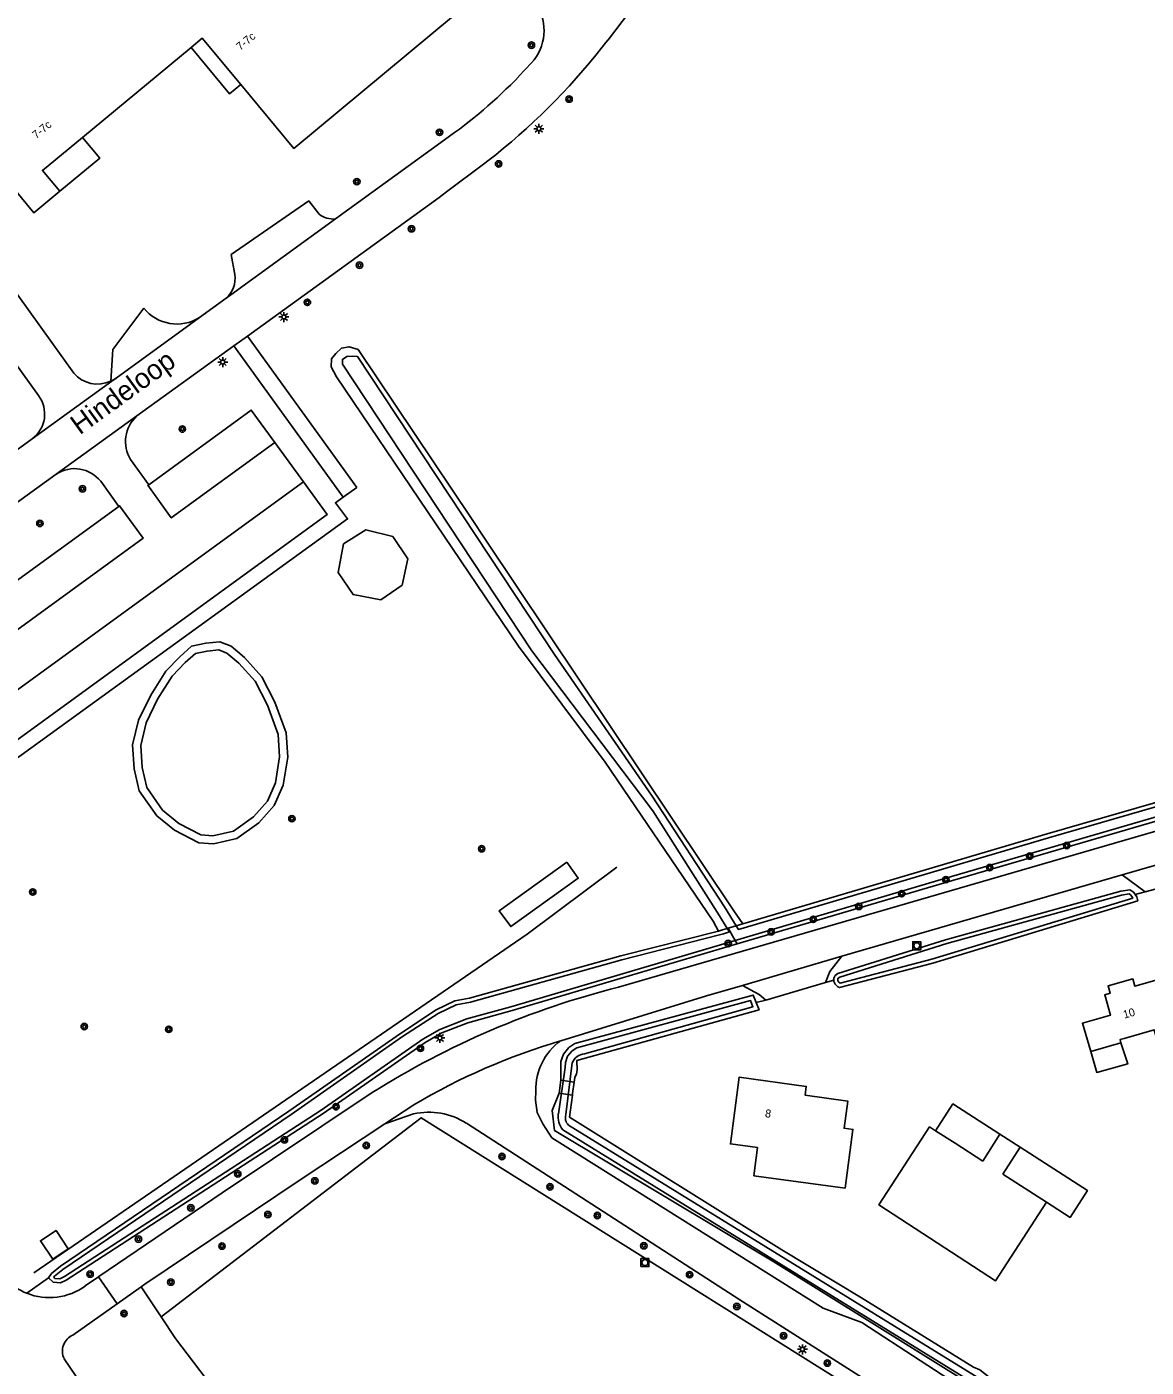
# Model space of a CAD drawing. Extents: x 141000 to 143000, y 400580 to 403500.
# Drawn here: x 141206 to 141345.9, y 402645.4 to 402812.9 of the extents above; entities that cross this region are included whole.
import ezdxf

# ---------------------------------------------------------------- set-up
doc = ezdxf.new("R2010")
doc.units = 0
for name, color, linetype in [('gg-afsc-erfafscheiding', 7, 'Continuous'), ('gg-afsc-hekwerk', 7, 'Continuous'), ('gg-anno-huisnummerreeks BGT', 7, 'Continuous'), ('gg-anno-openbare ruimte label', 7, 'Continuous'), ('gg-bbg-bijgebouw', 7, 'Continuous'), ('gg-bbg-gedigitaliseerde bijgebouw', 7, 'Continuous'), ('gg-bbg-hoofdgebouw', 7, 'Continuous'), ('gg-bbg-lage trafo', 7, 'Continuous'), ('gg-bbg-luifel en loopbrug', 7, 'Continuous'), ('gg-bbg-overig bouwwerk', 7, 'Continuous'), ('gg-knt-bronhoudergrens', 7, 'Continuous'), ('gg-knt-verharding', 7, 'Continuous'), ('gg-knt-verharding nz', 7, 'Continuous'), ('gg-kntw-bovenkant insteek waterloop', 7, 'Continuous'), ('gg-kntw-waterlijn', 7, 'Continuous'), ('gg-kwrk-kunstwerk niveau 01', 7, 'Continuous'), ('gt-grn-groengrens', 7, 'Continuous'), ('gt-grn-vlakafsluiter', 7, 'Continuous'), ('gt-grn-weggrens', 7, 'Continuous'), ('gt-symb-boom', 7, 'Continuous'), ('gt-symb-lichtmast', 7, 'Continuous'), ('gt-symb-rioolschacht', 7, 'Continuous')]:
    doc.layers.add(name, color=color, linetype=linetype)

# ---------------------------------------------------------------- blocks, each defined once
blk = doc.blocks.new('gt0-BOOM')
at = {"layer": 'gt-symb-boom'}
for radius in [0.4, 0.2]:
    blk.add_circle((0, 0), radius, dxfattribs=at)
blk = doc.blocks.new('gt0-LMAST')
at = {"layer": 'gt-symb-lichtmast'}
for p, q in [((-0.18, 0.17), (-0.45, 0.44)), ((-0.01, 0.25), (-0.01, 0.62)), ((0.17, 0.17), (0.44, 0.44)), ((-0.26, 0), (-0.63, 0)), ((-0.18, -0.18), (-0.45, -0.45)), ((-0.01, -0.25), (-0.01, -0.63)), ((0.44, -0.45), (0.17, -0.18)), ((0.24, 0), (0.62, 0))]:
    blk.add_line(p, q, dxfattribs=at)
blk.add_circle((-0.01, 0), 0.25, dxfattribs=at)
blk = doc.blocks.new('gt0-RS')
at = {"layer": 'gt-symb-rioolschacht'}
blk.add_lwpolyline([(-0.5, -0.5), (0.5, -0.5), (0.5, 0.5), (-0.5, 0.5)], close=True, dxfattribs=at)
blk.add_circle((0, 0), 0.375, dxfattribs=at)

msp = doc.modelspace()

# ---------------------------------------------------------------- linework, layer by layer
at = {"layer": 'gg-afsc-erfafscheiding'}
for p, q in [((141269.11, 402808.42), (141267.52, 402806.74)), ((141344.56, 402704.49), (141345.78, 402704.79)), ((141305.83, 402693.49), (141306.89, 402693.77)), ((141297.18, 402690.98), (141298.4, 402691.29))]:
    msp.add_line(p, q, dxfattribs=at)
at = {"layer": 'gg-afsc-hekwerk'}
msp.add_line((141245.56, 402754.13), (141247.27, 402755.33), dxfattribs=at)
for points in [[(141178.21, 402702.31), (141246.1, 402751.42), (141244.58, 402753.43), (141245.56, 402754.13)], [(141279.74, 402707.9), (141268.55, 402699.51), (141206.88, 402657.21)]]:
    msp.add_lwpolyline(points, dxfattribs=at)
at = {"layer": 'gg-bbg-bijgebouw'}
msp.add_line((141333.47, 402666.01), (141328.01, 402669.53), dxfattribs=at)
for points in [[(141319.61, 402674.95), (141318.86, 402675.43), (141312.52, 402665.67), (141327.1, 402656.2), (141333.47, 402666.01)], [(141325.49, 402671.16), (141322.04, 402673.38), (141319.61, 402674.95)]]:
    msp.add_lwpolyline(points, dxfattribs=at)
at = {"layer": 'gg-bbg-gedigitaliseerde bijgebouw'}
for p, q in [((141325.49, 402671.16), (141327.65, 402674.51)), ((141330.17, 402672.88), (141327.65, 402674.51)), ((141328.01, 402669.53), (141330.17, 402672.88))]:
    msp.add_line(p, q, dxfattribs=at)
at = {"layer": 'gg-bbg-hoofdgebouw'}
for p, q in [((141212.97, 402799.11), (141226.55, 402810.34)), ((141342.77, 402685.95), (141339, 402684.85))]:
    msp.add_line(p, q, dxfattribs=at)
for points in [[(141232.74, 402805.73), (141239.4, 402797.73), (141265, 402819.06), (141262.19, 402822.41), (141263.36, 402823.38)], [(141226.55, 402810.34), (141227.94, 402811.49), (141232.74, 402805.73)], [(141196.66, 402802.03), (141206.9, 402789.67), (141210.15, 402792.38)], [(141210.15, 402792.38), (141207.96, 402794.97), (141212.97, 402799.11)], [(141342.77, 402685.95), (141342.66, 402686.34), (141343.17, 402686.48), (141346.93, 402687.55), (141350.41, 402675.35), (141359.8, 402678.03), (141357.03, 402687.67), (141350.8, 402685.87), (141348.45, 402694.14), (141344.5, 402693.01), (141344.24, 402693.93), (141341.17, 402693.05), (141341.43, 402692.13), (141340.74, 402691.94), (141341.47, 402689.41), (141337.96, 402688.39), (141339, 402684.85)], [(141296.89, 402669.3), (141308.28, 402667.79), (141309.26, 402675.11), (141308.16, 402675.26), (141308.63, 402678.66), (141303.28, 402679.4), (141303.43, 402680.49), (141295.06, 402681.65), (141293.95, 402673.3), (141297.36, 402672.85), (141296.89, 402669.3)]]:
    msp.add_lwpolyline(points, dxfattribs=at)
at = {"layer": 'gg-bbg-lage trafo'}
msp.add_lwpolyline([(141211.19, 402660.18), (141209.24, 402658.89), (141207.71, 402661.19), (141209.66, 402662.48), (141211.19, 402660.18)], dxfattribs=at)
at = {"layer": 'gg-bbg-luifel en loopbrug'}
for points in [[(141226.55, 402810.34), (141231.33, 402804.56), (141232.74, 402805.73)], [(141210.15, 402792.38), (141215.13, 402796.5), (141212.97, 402799.11)], [(141342.77, 402685.95), (141343.62, 402683.31), (141339.74, 402682.23), (141339, 402684.85)], [(141327.65, 402674.51), (141321.77, 402678.3), (141319.61, 402674.95)], [(141333.47, 402666.01), (141336.41, 402664.11), (141338.57, 402667.46), (141330.17, 402672.88)]]:
    msp.add_lwpolyline(points, dxfattribs=at)
at = {"layer": 'gg-bbg-overig bouwwerk'}
for points in [[(141252.92, 402743.14), (141253.65, 402746.44), (141251.74, 402749.21), (141248.39, 402750.05), (141245.58, 402748.29), (141244.94, 402744.74), (141246.79, 402741.97), (141250.26, 402741.3), (141252.92, 402743.14)], [(141273.52, 402708.5), (141265.07, 402702.45), (141266.49, 402700.46), (141274.94, 402706.51), (141273.52, 402708.5)]]:
    msp.add_lwpolyline(points, dxfattribs=at)
at = {"layer": 'gg-knt-bronhoudergrens'}
for p, q in [((141222.79, 402651.7), (141224.58, 402648.98)), ((141224.58, 402648.98), (141229.11, 402643.06))]:
    msp.add_line(p, q, dxfattribs=at)
msp.add_lwpolyline([(141363.07, 402606.73), (141327.61, 402631.24), (141255.32, 402676.57), (141222.79, 402651.7)], dxfattribs=at)
at = {"layer": 'gg-knt-verharding'}
for p, q in [((141191.61, 402797.8), (141211.89, 402769.63)), ((141258.23, 402798.81), (141244.58, 402788.91)), ((141207.47, 402766.83), (141187.44, 402794.64)), ((141241.26, 402791.18), (141242.55, 402789.49)), ((141244.58, 402788.91), (141231.5, 402779.44)), ((141232, 402781.95), (141231.57, 402784.48)), ((141230.91, 402779.01), (141227.59, 402776.59)), ((141231.5, 402779.44), (141230.91, 402779.01)), ((141226.5, 402775.8), (141217.16, 402769.03)), ((141227.59, 402776.59), (141226.5, 402775.8)), ((141231.88, 402773.04), (141233.59, 402774.28)), ((141233.59, 402774.28), (141247.27, 402755.33)), ((141216.77, 402772.6), (141216.5, 402768.64)), ((141219.76, 402764.29), (141231.88, 402773.04)), ((141231.88, 402773.04), (141245.56, 402754.13)), ((141217.16, 402769.03), (141216.64, 402768.65)), ((141216.64, 402768.65), (141206.67, 402761.42)), ((141209.69, 402757.02), (141219.76, 402764.29)), ((141240.61, 402756.07), (141237.03, 402760.96)), ((141221.24, 402755.69), (141218.97, 402758.84)), ((141240.61, 402756.07), (141182.5, 402713.85)), ((141215.24, 402756.12), (141217.51, 402752.99)), ((141217.51, 402752.99), (141190.98, 402733.72)), ((141411.79, 402731.14), (141279.97, 402692.9)), ((141307.88, 402696.75), (141342.93, 402706.95)), ((141342.93, 402706.95), (141345.78, 402704.79)), ((141351.67, 402706.4), (141345.78, 402704.79)), ((141305.83, 402693.49), (141298.4, 402691.29)), ((141250.77, 402675.82), (141254.36, 402677.05)), ((141214.95, 402656.67), (141213.32, 402655.56)), ((141214.95, 402656.67), (141217.32, 402653.33)), ((141211.76, 402649.4), (141217.32, 402653.33)), ((141212.8, 402643.31), (141210.67, 402646.46))]:
    msp.add_line(p, q, dxfattribs=at)
for points in [[(141233.59, 402774.28), (141257.53, 402791.58), (141258.47, 402792.29), (141263.26, 402795.89), (141263.62, 402796.16)], [(141216.5, 402768.64), (141216.84, 402768.82), (141217.16, 402769.03)], [(141221.24, 402755.69), (141234.07, 402765.02), (141237.03, 402760.96)], [(141206.67, 402761.42), (141196.62, 402754.14), (141192.21, 402750.94)], [(141237.03, 402760.96), (141224.07, 402751.54), (141221.14, 402755.62), (141221.24, 402755.69)], [(141189.48, 402742.38), (141199.98, 402750), (141209.69, 402757.02)], [(141240.61, 402756.07), (141243.56, 402751.99), (141185.46, 402709.78), (141182.5, 402713.85)], [(141217.51, 402752.99), (141217.61, 402753.06), (141220.56, 402749.02), (141193.83, 402729.59), (141190.88, 402733.65), (141190.98, 402733.72)], [(141307.88, 402696.75), (141306.37, 402694.84), (141305.83, 402693.49)], [(141272.74, 402686.2), (141290.95, 402691.8), (141295.47, 402693.12)], [(141295.47, 402693.12), (141297.56, 402691.97), (141298.4, 402691.29)], [(141324.96, 402641.5), (141310.38, 402650.99), (141305.55, 402652.78), (141273.28, 402673.01), (141271.64, 402674.08), (141270.49, 402675.82), (141269.81, 402677.24), (141269.59, 402678.78), (141269.64, 402679.93)], [(141249.18, 402679.72), (141230.44, 402667.18), (141215.02, 402656.72), (141214.95, 402656.67)], [(141220.32, 402655.45), (141220.77, 402655.77), (141240.06, 402668.75), (141250.77, 402675.82)], [(141260.95, 402675.89), (141295.14, 402653.83), (141324.89, 402634.91), (141364.96, 402609.57)], [(141217.32, 402653.33), (141217.32, 402653.33), (141220.32, 402655.45)]]:
    msp.add_lwpolyline(points, dxfattribs=at)
for centre, radius, start, end in [((141153.37, 402909.18), 158.99, 321.5784, 330.2828), ((141264.63, 402812.46), 6.03, 317.9723, 31.9761), ((141214.33, 402860.07), 80.71, 307.6433, 321.9991), ((141222.36, 402850.24), 62.71, 304.8955, 316.0699), ((141244.36, 402791.96), 3.06, 233.7555, 274.115), ((141228.71, 402781.5), 3.33, 311.4812, 7.8421), ((141224.77, 402781.11), 5.33, 218.8919, 301.9381), ((141214.85, 402772.18), 3.91, 220.6984, 294.8949), ((141204.38, 402764.53), 3.86, 306.4726, 36.7072), ((141222.63, 402761.09), 4.29, 131.9046, 211.6556), ((141211.98, 402753.53), 4.17, 38.4638, 123.2316), ((141306.49, 402588.35), 107.86, 104.2323, 122.0957), ((141277.14, 402680.12), 7.51, 125.9366, 181.4607), ((141256.28, 402668.7), 8.57, 57.0115, 103.0092), ((141208.83, 402661.7), 7.61, 224.0966, 248.2539), ((141208.83, 402661.7), 7.61, 248.2585, 306.1901), ((141212.63, 402647.41), 2.17, 113.4929, 205.8061)]:
    msp.add_arc(centre, radius, start, end, dxfattribs=at)
at = {"layer": 'gg-knt-verharding nz'}
for p, q in [((141342.93, 402706.95), (141352.62, 402709.76)), ((141295.47, 402693.12), (141307.88, 402696.75))]:
    msp.add_line(p, q, dxfattribs=at)
at = {"layer": 'gg-kntw-bovenkant insteek waterloop'}
for points in [[(141244.06, 402770.44), (141244.08, 402771.44), (141244.62, 402772.08), (141245.34, 402772.76), (141246.3, 402772.93), (141247.41, 402772.58), (141261.5, 402751.61), (141263.4, 402748.77), (141294.39, 402702.44), (141295.49, 402700.8)], [(141292.45, 402699.91), (141291.78, 402701.13), (141278.32, 402721.01), (141267.45, 402735.51), (141244.72, 402769.16), (141244.06, 402770.44)], [(141232.25, 402711.46), (141235.02, 402713.44), (141236.93, 402715.6), (141238.06, 402718.14), (141238.62, 402721.65), (141238.43, 402724.67), (141237.02, 402728.53), (141235.38, 402731.7), (141233.2, 402734.09), (141231.56, 402735.5), (141230.13, 402736.07), (141228.39, 402735.9), (141226.61, 402735.5), (141225.12, 402734.2), (141223.39, 402732.39), (141221.49, 402729.38), (141219.97, 402726.27), (141219.23, 402723.2), (141219.42, 402720.2), (141220.06, 402717.42), (141222.24, 402714.31), (141224.46, 402712.5), (141227.5, 402710.95), (141229.33, 402710.81), (141232.25, 402711.46)], [(141294.81, 402698.29), (141320.71, 402705.95), (141358.59, 402716.98), (141380.25, 402723.21), (141405.81, 402730.8), (141416.79, 402734.5), (141417.38, 402735.17)], [(141295.49, 402700.8), (141333.56, 402712.04), (141380.23, 402725.52), (141414.51, 402735.47)], [(141344.56, 402704.49), (141344.54, 402704.52), (141344.31, 402704.81), (141343.89, 402705.08), (141342.74, 402704.88), (141320.84, 402698.83), (141307.39, 402694.61), (141307.03, 402694.34), (141306.88, 402694.01), (141306.89, 402693.77)], [(141344.56, 402704.49), (141344.74, 402704.19), (141344.88, 402703.69), (141319.26, 402695.91), (141307.57, 402692.84), (141307.38, 402692.95), (141307.04, 402693.28), (141306.89, 402693.62), (141306.89, 402693.77)], [(141208.73, 402656.57), (141209.11, 402657.1), (141210.22, 402658.02), (141238.76, 402677.39), (141252.7, 402687.12), (141257.18, 402690.06), (141259.52, 402691.17), (141261.33, 402691.53), (141280.24, 402696.8), (141292.45, 402699.91)], [(141294.81, 402698.29), (141266.66, 402689.97), (141261.15, 402688.45), (141257.87, 402687.17), (141255.79, 402685.96), (141243.07, 402677.11), (141210.94, 402656.28), (141210.21, 402655.96), (141209.3, 402656.02), (141208.73, 402656.57)], [(141272.77, 402681.25), (141272.75, 402682.83), (141272.77, 402683.59), (141273.08, 402684.53), (141273.77, 402685.36), (141274.5, 402685.85), (141296.81, 402691.91), (141297.18, 402690.98)], [(141297.18, 402690.98), (141297.53, 402690.07), (141274.74, 402683.71), (141274.82, 402682.54), (141274.72, 402682.06), (141274.5, 402681.61), (141274.42, 402681)], [(141326.29, 402644.17), (141326.16, 402643.59), (141325.63, 402643.04), (141325.28, 402642.74), (141325.1, 402642.7), (141322.81, 402643.98), (141299.58, 402658.44), (141271.98, 402674.97), (141271.68, 402677.48), (141272.53, 402679.66)], [(141326.29, 402644.17), (141325.12, 402645.08), (141324.32, 402645.4), (141310.35, 402654.08), (141300.39, 402660.06), (141273.84, 402676.66), (141274.21, 402679.41)]]:
    msp.add_lwpolyline(points, dxfattribs=at)
at = {"layer": 'gg-kntw-waterlijn'}
for p, q in [((141273.4, 402676.96), (141274.19, 402683.43)), ((141273, 402675.06), (141325.07, 402642.94)), ((141325.54, 402643.7), (141273.71, 402675.66))]:
    msp.add_line(p, q, dxfattribs=at)
for points in [[(141293.55, 402700.23), (141292.58, 402701.81), (141284.24, 402714.92), (141269.14, 402734.94), (141245.46, 402770.77), (141245.45, 402771.36), (141245.99, 402771.7), (141246.7, 402771.76), (141247.36, 402771.7), (141271.95, 402734.47), (141284.18, 402716.78), (141293.22, 402702.94), (141294.68, 402700.57)], [(141294.55, 402698.74), (141320.57, 402706.43), (141358.45, 402717.46), (141380.11, 402723.69), (141405.66, 402731.28), (141416.5, 402734.93), (141416.89, 402735.1), (141417.01, 402735.25), (141417.01, 402735.4), (141416.93, 402735.49), (141416.83, 402735.56), (141416.39, 402735.5)], [(141294.68, 402700.57), (141294.95, 402700.12), (141333.7, 402711.56), (141380.37, 402725.04), (141416.39, 402735.5)], [(141231.84, 402712.39), (141234.35, 402714.19), (141236.08, 402716.15), (141237.1, 402718.43), (141237.61, 402721.69), (141237.44, 402724.46), (141236.1, 402728.13), (141234.55, 402731.12), (141232.5, 402733.37), (141231.03, 402734.63), (141229.99, 402735.05), (141228.55, 402734.91), (141227.08, 402734.58), (141225.81, 402733.48), (141224.18, 402731.78), (141222.36, 402728.89), (141220.92, 402725.93), (141220.24, 402723.11), (141220.41, 402720.34), (141220.99, 402717.84), (141222.98, 402715), (141225.01, 402713.35), (141227.78, 402711.93), (141229.26, 402711.82), (141231.84, 402712.39)], [(141343.78, 402704.55), (141342.85, 402704.38), (141320.99, 402698.34), (141307.62, 402694.15), (141307.44, 402694.01), (141307.39, 402693.9), (141307.4, 402693.78), (141307.4, 402693.73), (141307.46, 402693.58), (141307.66, 402693.39), (141319.12, 402696.4), (141344.24, 402704.03), (141344.12, 402704.23), (141343.96, 402704.43), (141343.78, 402704.55)], [(141294.55, 402698.74), (141266.52, 402690.45), (141260.99, 402688.93), (141257.65, 402687.62), (141255.52, 402686.38), (141242.79, 402677.52), (141210.7, 402656.72), (141210.12, 402656.46), (141209.52, 402656.5), (141209.39, 402656.63), (141209.48, 402656.76), (141210.52, 402657.62), (141239.05, 402676.98), (141252.98, 402686.71), (141257.43, 402689.62), (141259.68, 402690.69), (141261.45, 402691.04), (141280.37, 402696.31), (141292.58, 402699.43), (141293.09, 402699.58), (141293.83, 402699.79), (141293.55, 402700.23)], [(141275.7, 402684.57), (141296.77, 402690.45), (141296.64, 402690.77), (141296.47, 402691.22), (141274.74, 402685.32), (141274.16, 402684.93), (141273.59, 402684.25), (141273.34, 402683.49), (141273.32, 402682.86), (141272.45, 402677.06)]]:
    msp.add_lwpolyline(points, dxfattribs=at)
for centre, radius, start, end in [((141275.88, 402682.75), 1.83, 95.6923, 157.9385), ((141275.05, 402676.7), 2.63, 171.9992, 218.7042), ((141274.52, 402676.55), 1.2, 160.1666, 227.5718)]:
    msp.add_arc(centre, radius, start, end, dxfattribs=at)
at = {"layer": 'gg-kwrk-kunstwerk niveau 01'}
for p, q in [((141272.53, 402679.66), (141272.77, 402681.25)), ((141272.77, 402681.25), (141274.42, 402681)), ((141272.53, 402679.66), (141274.21, 402679.41))]:
    msp.add_line(p, q, dxfattribs=at)
msp.add_lwpolyline([(141274.42, 402681), (141274.23, 402679.62), (141274.21, 402679.41)], dxfattribs=at)
at = {"layer": 'gt-grn-groengrens'}
for p, q in [((141206.01, 402654.63), (141208.73, 402656.57)), ((141222.79, 402651.7), (141220.32, 402655.45))]:
    msp.add_line(p, q, dxfattribs=at)
at = {"layer": 'gt-grn-vlakafsluiter'}
for p, q in [((141231.57, 402784.48), (141241.26, 402791.18)), ((141216.77, 402772.6), (141220.62, 402777.77)), ((141292.45, 402699.91), (141292.95, 402700.06)), ((141292.95, 402700.06), (141293.55, 402700.23)), ((141293.55, 402700.23), (141293.67, 402700.27)), ((141293.67, 402700.27), (141294.68, 402700.57)), ((141294.55, 402698.74), (141293.67, 402700.27)), ((141295.49, 402700.8), (141294.68, 402700.57)), ((141294.81, 402698.29), (141294.55, 402698.74))]:
    msp.add_line(p, q, dxfattribs=at)
at = {"layer": 'gt-grn-weggrens'}
msp.add_line((141250.77, 402675.82), (141254.37, 402678.19), dxfattribs=at)
msp.add_arc((141296.42, 402606.85), 82.81, 106.6211, 120.5195, dxfattribs=at)

# ---------------------------------------------------------------- block references
at = {"layer": 'gt-symb-boom'}
for p in [(141269.08, 402810.63), (141273.79, 402803.89), (141257.59, 402799.74), (141264.98, 402795.79), (141247.26, 402793.57), (141254.09, 402787.68), (141247.59, 402783.13), (141241.08, 402778.49), (141225.45, 402762.65), (141212.96, 402755.18), (141207.64, 402750.86), (141239.14, 402713.95), (141262.86, 402710.19), (141335.99, 402710.59), (141331.37, 402709.28), (141320.89, 402706.33), (141326.36, 402707.84), (141206.75, 402704.79), (141310, 402702.98), (141315.37, 402704.58), (141304.32, 402701.37), (141299.04, 402699.8), (141293.68, 402698.35), (141213.19, 402687.97), (141223.75, 402687.62), (141255.21, 402685.25), (141244.65, 402677.95), (141238.21, 402673.8), (141248.44, 402673.11), (141265.4, 402671.73), (141232.38, 402669.55), (141242.01, 402668.68), (141271.4, 402667.94), (141226.51, 402665.31), (141236.14, 402664.48), (141277.32, 402664.36), (141219.97, 402661.4), (141230.4, 402660.53), (141283.13, 402660.57), (141213.92, 402657.03), (141224.01, 402656.03), (141288.85, 402656.96), (141294.76, 402652.98), (141218.16, 402652.11), (141300.6, 402649.32), (141306.07, 402645.91)]:
    msp.add_blockref('gt0-BOOM', p, dxfattribs=at)
at = {"layer": 'gt-symb-lichtmast'}
for p in [(141270.02, 402800.19), (141238.15, 402776.66), (141230.5, 402771.03), (141257.65, 402686.55), (141302.97, 402647.63)]:
    msp.add_blockref('gt0-LMAST', p, dxfattribs=at)
at = {"layer": 'gt-symb-rioolschacht'}
for p in [(141317.25, 402698.08), (141283.27, 402658.47)]:
    msp.add_blockref('gt0-RS', p, dxfattribs=at)

# ---------------------------------------------------------------- texts
at = {"layer": 'gg-anno-huisnummerreeks BGT'}
for s, rotation, p in [('7-7c', 39.8, (141232.69, 402809.91)), ('7-7c', 39.6, (141207.19, 402798.87)), ('10', 15.9, (141343.19, 402688.95)), ('8', 352.1, (141298.24, 402676.66))]:
    msp.add_text(s, height=1, rotation=rotation, dxfattribs=at).set_placement(p)
at = {"layer": 'gg-anno-openbare ruimte label'}
msp.add_text('Hindeloop', height=2.5, rotation=35.9, dxfattribs=at).set_placement((141212.63, 402761.85))

doc.saveas('drawing.dxf')
